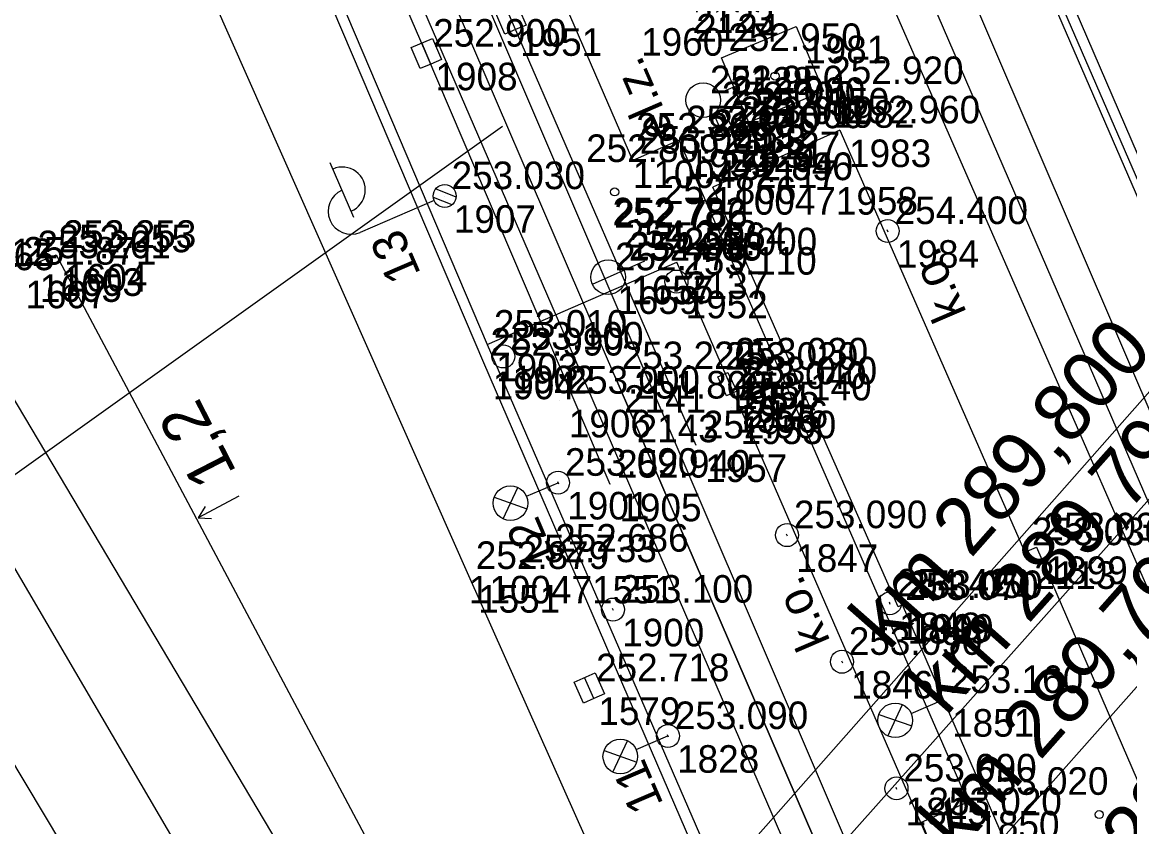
# Model space of a CAD drawing. Extents: x -496688 to -495455, y -1089309 to -1088026.
# Drawn here: x -496075.33 to -496027.15, y -1088401.59 to -1088366.58 of the extents above; entities that cross this region are included whole.
import ezdxf

# ---------------------------------------------------------------- set-up
doc = ezdxf.new("R2010")
doc.units = 0
for name, color, linetype in [('Vrstva 1', 7, 'Continuous'), ('Vrstva 13', 7, 'Continuous'), ('Vrstva 16', 7, 'Continuous'), ('Vrstva 17', 7, 'Continuous'), ('Vrstva 23', 7, 'Continuous'), ('Vrstva 25', 7, 'Continuous'), ('Vrstva 29', 7, 'Continuous'), ('Vrstva 36', 7, 'Continuous'), ('Vrstva 43', 7, 'Continuous'), ('Vrstva 47', 7, 'Continuous'), ('Vrstva 50', 7, 'Continuous'), ('Vrstva 51', 7, 'Continuous'), ('Vrstva 55', 7, 'Continuous'), ('Vrstva 59', 7, 'Continuous'), ('Vrstva 6', 7, 'Continuous'), ('Vrstva 60', 7, 'Continuous'), ('Vrstva 61', 7, 'Continuous')]:
    doc.layers.add(name, color=color, linetype=linetype)

msp = doc.modelspace()

# ---------------------------------------------------------------- linework, layer by layer
at = {"layer": 'Vrstva 1'}
for points in [[(-496002.91, -1088487.94), (-496012.12, -1088468.34), (-496019.16, -1088452.48), (-496027.13, -1088434.02), (-496033.75, -1088418.68), (-496038, -1088408.8), (-496049, -1088383.26), (-496049.55, -1088381.98), (-496058.24, -1088361.79), (-496064.07, -1088348.3)], [(-496001.99, -1088443.76), (-496010.04, -1088425.17), (-496041.61, -1088352.14), (-496042.12, -1088351.02)], [(-496016.532, -1088478.726), (-496026.498, -1088456.559), (-496035.879, -1088435.575), (-496046.648, -1088411.427), (-496055.896, -1088390.674), (-496071.432, -1088355.64)]]:
    msp.add_lwpolyline(points, dxfattribs=at)
at = {"layer": 'Vrstva 13'}
msp.add_line((-496065.907, -1088387.212), (-496067.673, -1088388.151), dxfattribs=at)
for points in [[(-496006.04, -1088421.27), (-496039.66, -1088343.83)], [(-496061.92, -1088348.13), (-496054.07, -1088366.45), (-496046.02, -1088384.99)], [(-496049.75, -1088386.7), (-496057.75, -1088367.95), (-496065.63, -1088349.73)], [(-496080.12, -1088377.498), (-496074.961, -1088377.155), (-496073.856, -1088376.703), (-496059.337, -1088404.014), (-496053.843, -1088414.068), (-496043.578, -1088433.154), (-496032.169, -1088453.826), (-496029.326, -1088459.298)], [(-496067.372, -1088387.651), (-496067.673, -1088388.151), (-496067.091, -1088388.181)]]:
    msp.add_lwpolyline(points, dxfattribs=at)
at = {"layer": 'Vrstva 16'}
for p, q in [((-496041.7, -1088339.8), (-495977.29, -1088488.74)), ((-496048.77, -1088372.6), (-496062.47, -1088340.95)), ((-496046.75, -1088371.72), (-496048.77, -1088372.6)), ((-496034.18, -1088400.5), (-496046.75, -1088371.72)), ((-496036.21, -1088401.39), (-496034.18, -1088400.5))]:
    msp.add_line(p, q, dxfattribs=at)
for points in [[(-496079.26, -1088341.75), (-496070.21, -1088346.6), (-496069.83, -1088346), (-496055.11, -1088380.61)], [(-496036.29, -1088409.7), (-496064.15, -1088344.68), (-496066.65, -1088345.76), (-496038.55, -1088410.67)], [(-496040.8, -1088349.66), (-495980.44, -1088490.38), (-495970.84, -1088512.75)], [(-496043.99, -1088350.95), (-496001.7, -1088447.58), (-495982.81, -1088491.28), (-495972.63, -1088514.67), (-495960.36, -1088543.09), (-495953.91, -1088556.79), (-495957.95, -1088558.44), (-495964.6, -1088544.16), (-495976.56, -1088516.39), (-495986.4, -1088493.44), (-495993.77, -1088476.63), (-495996.44, -1088470.15), (-496005.77, -1088448.81)], [(-496049.55, -1088381.98), (-496049, -1088383.26), (-496038, -1088408.8), (-496037.45, -1088410.08)], [(-496036.21, -1088401.39), (-496032.08, -1088411.59)]]:
    msp.add_lwpolyline(points, dxfattribs=at)
at = {"layer": 'Vrstva 17'}
msp.add_lwpolyline([(-496095, -1088344.78), (-496090.4, -1088338.56), (-496087.52, -1088339.34), (-496079.62, -1088343.92), (-496077.74, -1088344.53), (-496072.27, -1088346.17), (-496070.01, -1088346.79), (-496055.26, -1088381.39), (-496028.35, -1088443.67), (-496017.15, -1088468.64), (-496004.62, -1088495.93), (-495995.82, -1088511.25), (-495975.79, -1088547.86), (-495946.8, -1088592.09), (-495933.46, -1088582.38), (-495946.67, -1088555.94), (-495952.97, -1088543.38), (-495959.99, -1088527.36), (-495989.63, -1088458.09), (-496005.03, -1088422.44), (-496022.96, -1088381.24), (-496041.83, -1088337.51), (-496069.73, -1088316.93)], dxfattribs=at)
at = {"layer": 'Vrstva 23'}
for p, q in [((-496044.91, -1088368.14), (-496041.67, -1088366.77)), ((-496055.11, -1088380.61), (-496046.85, -1088377.03))]:
    msp.add_line(p, q, dxfattribs=at)
for points in [[(-496041.67, -1088366.77), (-496040.48, -1088369.58), (-496043.72, -1088370.95), (-496044.91, -1088368.14)], [(-496039.76, -1088371.29), (-496045.29, -1088373.76)], [(-496039.76, -1088371.29), (-496031.71, -1088389.64), (-496031.21, -1088389.43), (-496005.59, -1088448.65)], [(-496037.22, -1088392.02), (-496045.29, -1088373.76)], [(-496055.11, -1088380.61), (-496040.15, -1088415.06), (-496031.83, -1088411.54), (-496046.85, -1088377.03)], [(-496029.66, -1088408.99), (-496037.04, -1088391.94), (-496037.22, -1088392.02)]]:
    msp.add_lwpolyline(points, dxfattribs=at)
at = {"layer": 'Vrstva 25'}
for p, q in [((-496060.901, -1088375.088), (-496061.929, -1088372.7)), ((-496056.454, -1088374.197), (-496057.344, -1088373.843)), ((-496057.409, -1088374.348), (-496060.624, -1088375.731)), ((-496056.627, -1088374.531), (-496057.444, -1088374.206)), ((-496037.66, -1088375.716), (-496037.7, -1088375.624)), ((-496054.413, -1088388.191), (-496053.775, -1088386.825)), ((-496053.398, -1088387.213), (-496052.02, -1088386.62)), ((-496054.8, -1088387.252), (-496053.377, -1088387.753)), ((-496037.571, -1088391.916), (-496037.609, -1088391.824)), ((-496036.658, -1088396.663), (-496035.28, -1088396.07)), ((-496037.673, -1088397.641), (-496037.035, -1088396.275)), ((-496038.06, -1088396.702), (-496036.637, -1088397.203)), ((-496049.633, -1088399.211), (-496048.995, -1088397.845)), ((-496048.618, -1088398.233), (-496047.24, -1088397.64)), ((-496050.02, -1088398.272), (-496048.597, -1088398.773))]:
    msp.add_line(p, q, dxfattribs=at)
for centre, radius in [((-496056.95, -1088374.15), 0.5), ((-496056.95, -1088374.15), 0.5), ((-496037.68, -1088375.67), 0.5), ((-496054.091, -1088387.509), 0.754), ((-496037.59, -1088391.87), 0.5), ((-496037.351, -1088396.959), 0.754), ((-496049.311, -1088398.529), 0.754)]:
    msp.add_circle(centre, radius, dxfattribs=at)
for centre, start, end in [((-496061.404, -1088373.889), 292.585, 113.9902), ((-496061.019, -1088374.813), 113.2876, 293.2876)]:
    msp.add_arc(centre, 1, start, end, dxfattribs=at)
at = {"layer": 'Vrstva 29'}
msp.add_lwpolyline([(-496089.818, -1088342.239), (-496104.91, -1088361.836), (-496082.668, -1088391.264), (-496054.437, -1088371.109)], dxfattribs=at)
at = {"layer": 'Vrstva 36'}
msp.add_line((-496045.015, -1088369.681), (-496044.097, -1088369.284), dxfattribs=at)
for points in [[(-496045.2, -1088370.67), (-496044.76, -1088370.49), (-496044.41, -1088371.32), (-496044.84, -1088371.5), (-496045.2, -1088370.67)], [(-496045.07, -1088382.01), (-496044.63, -1088381.82), (-496044.24, -1088382.64), (-496044.7, -1088382.84), (-496045.07, -1088382.01)]]:
    msp.add_lwpolyline(points, dxfattribs=at)
msp.add_circle((-496045.71, -1088369.979), 0.757, dxfattribs=at)
at = {"layer": 'Vrstva 43'}
for points in [[(-496053.872, -1088366.909), (-496054.332, -1088367.107), (-496054.727, -1088366.188), (-496053.808, -1088365.793), (-496053.413, -1088366.712), (-496053.872, -1088366.909), (-496054.268, -1088365.991)], [(-496057.552, -1088368.409), (-496058.012, -1088368.607), (-496058.407, -1088367.688), (-496057.488, -1088367.293), (-496057.093, -1088368.212), (-496057.552, -1088368.409), (-496057.948, -1088367.491)], [(-496050.463, -1088396.016), (-496050.92, -1088396.219), (-496051.326, -1088395.305), (-496050.412, -1088394.899), (-496050.006, -1088395.813), (-496050.463, -1088396.016), (-496050.869, -1088395.102)]]:
    msp.add_lwpolyline(points, dxfattribs=at)
at = {"layer": 'Vrstva 47'}
msp.add_line((-496050.526, -1088377.981), (-496048.238, -1088376.975), dxfattribs=at)
msp.add_circle((-496049.84, -1088377.679), 0.75, dxfattribs=at)
at = {"layer": 'Vrstva 50'}
for p, q in [((-496046.85, -1088377.916), (-496046.89, -1088377.824)), ((-496054.38, -1088381.176), (-496054.42, -1088381.084)), ((-496052.04, -1088386.574), (-496052, -1088386.666)), ((-496042.04, -1088388.946), (-496042.08, -1088388.854)), ((-496049.61, -1088392.186), (-496049.65, -1088392.094)), ((-496039.69, -1088394.364), (-496039.65, -1088394.456)), ((-496047.22, -1088397.686), (-496047.26, -1088397.594)), ((-496037.28, -1088399.966), (-496037.32, -1088399.874))]:
    msp.add_line(p, q, dxfattribs=at)
for centre in [(-496046.87, -1088377.87), (-496054.4, -1088381.13), (-496052.02, -1088386.62), (-496042.06, -1088388.9), (-496049.63, -1088392.14), (-496039.67, -1088394.41), (-496047.24, -1088397.64), (-496037.3, -1088399.92)]:
    msp.add_circle(centre, 0.5, dxfattribs=at)
at = {"layer": 'Vrstva 51'}
msp.add_lwpolyline([(-495977.447, -1088558.133), (-495981.17, -1088560.671), (-496005.397, -1088519.367), (-496022.661, -1088489.693), (-496025.004, -1088485.709), (-496027.464, -1088481.551), (-496045.275, -1088451.173), (-496063.404, -1088419.387), (-496086.159, -1088381.351), (-496097.371, -1088363.41), (-496092.898, -1088360.245), (-496082.247, -1088379.121), (-496059.799, -1088417.46), (-496050.414, -1088433.44), (-496038.244, -1088454.083), (-496022.567, -1088481.185), (-496019.429, -1088486.595), (-496001.625, -1088516.799), (-495977.447, -1088558.133)], dxfattribs=at)
at = {"layer": 'Vrstva 55'}
msp.add_lwpolyline([(-495954.14, -1088589.68), (-495962.8, -1088574.76), (-495975.81, -1088551.75), (-495980.15, -1088535.95), (-495988.3, -1088530.08), (-496096.94, -1088347.2)], dxfattribs=at)
at = {"layer": 'Vrstva 59'}
for centre in [(-496042.583, -1088368.932), (-496049.557, -1088373.972), (-496028.482, -1088401.057)]:
    msp.add_circle(centre, 0.175, dxfattribs=at)
at = {"layer": 'Vrstva 6'}
for p, q in [((-496127.419, -1088497.214), (-496021.846, -1088377.607)), ((-496094.37, -1088463.824), (-496019.966, -1088380.195)), ((-496084.128, -1088460.218), (-496019.428, -1088387.106))]:
    msp.add_line(p, q, dxfattribs=at)
at = {"layer": 'Vrstva 60'}
for p, q in [((-496041.67, -1088366.77), (-496041.67, -1088366.77)), ((-496057.75, -1088367.95), (-496057.75, -1088367.95)), ((-496044.91, -1088368.14), (-496044.91, -1088368.14)), ((-496040.48, -1088369.58), (-496040.48, -1088369.58)), ((-496045.71, -1088369.98), (-496045.71, -1088369.98)), ((-496044.76, -1088370.49), (-496044.76, -1088370.49)), ((-496045.2, -1088370.67), (-496045.2, -1088370.67)), ((-496043.72, -1088370.95), (-496043.72, -1088370.95)), ((-496044.84, -1088371.5), (-496044.84, -1088371.5)), ((-496044.41, -1088371.32), (-496044.41, -1088371.32)), ((-496039.76, -1088371.29), (-496039.76, -1088371.29)), ((-496046.75, -1088371.72), (-496046.75, -1088371.72)), ((-496048.77, -1088372.6), (-496048.77, -1088372.6)), ((-496045.29, -1088373.76), (-496045.29, -1088373.76)), ((-496056.95, -1088374.15), (-496056.95, -1088374.15)), ((-496037.68, -1088375.67), (-496037.68, -1088375.67)), ((-496073.856, -1088376.703), (-496073.856, -1088376.703)), ((-496073.856, -1088376.703), (-496073.856, -1088376.703)), ((-496074.961, -1088377.155), (-496074.961, -1088377.155)), ((-496074.961, -1088377.155), (-496074.961, -1088377.155)), ((-496074.047, -1088376.895), (-496074.047, -1088376.895)), ((-496074.047, -1088376.895), (-496074.047, -1088376.895)), ((-496049.244, -1088377.259), (-496049.244, -1088377.259)), ((-496049.244, -1088377.259), (-496049.244, -1088377.259)), ((-496049.224, -1088377.211), (-496049.224, -1088377.211)), ((-496049.224, -1088377.211), (-496049.224, -1088377.211)), ((-496046.85, -1088377.03), (-496046.85, -1088377.03)), ((-496049.84, -1088377.679), (-496049.84, -1088377.679)), ((-496049.84, -1088377.679), (-496049.84, -1088377.679)), ((-496046.87, -1088377.87), (-496046.87, -1088377.87)), ((-496055.11, -1088380.61), (-496055.11, -1088380.61)), ((-496054.4, -1088381.13), (-496054.4, -1088381.13)), ((-496055.26, -1088381.39), (-496055.26, -1088381.39)), ((-496049.55, -1088381.98), (-496049.55, -1088381.98)), ((-496045.07, -1088382.01), (-496045.07, -1088382.01)), ((-496044.63, -1088381.82), (-496044.63, -1088381.82)), ((-496051.95, -1088383.05), (-496051.95, -1088383.05)), ((-496044.7, -1088382.84), (-496044.7, -1088382.84)), ((-496044.24, -1088382.64), (-496044.24, -1088382.64)), ((-496049, -1088383.26), (-496049, -1088383.26)), ((-496044.48, -1088383.34), (-496044.48, -1088383.34)), ((-496046.02, -1088384.99), (-496046.02, -1088384.99)), ((-496052.02, -1088386.62), (-496052.02, -1088386.62)), ((-496049.75, -1088386.7), (-496049.75, -1088386.7)), ((-496042.06, -1088388.9), (-496042.06, -1088388.9)), ((-496031.71, -1088389.64), (-496031.71, -1088389.64)), ((-496031.21, -1088389.43), (-496031.21, -1088389.43)), ((-496055.896, -1088390.674), (-496055.896, -1088390.674)), ((-496055.896, -1088390.674), (-496055.896, -1088390.674)), ((-496049.63, -1088392.14), (-496049.63, -1088392.14)), ((-496037.59, -1088391.87), (-496037.59, -1088391.87)), ((-496037.22, -1088392.02), (-496037.22, -1088392.02)), ((-496037.04, -1088391.94), (-496037.04, -1088391.94)), ((-496039.67, -1088394.41), (-496039.67, -1088394.41)), ((-496050.666, -1088395.559), (-496050.666, -1088395.559)), ((-496050.666, -1088395.559), (-496050.666, -1088395.559)), ((-496035.28, -1088396.07), (-496035.28, -1088396.07)), ((-496047.24, -1088397.64), (-496047.24, -1088397.64)), ((-496037.3, -1088399.92), (-496037.3, -1088399.92)), ((-496034.18, -1088400.5), (-496034.18, -1088400.5)), ((-496036.21, -1088401.39), (-496036.21, -1088401.39))]:
    msp.add_line(p, q, dxfattribs=at)

# ---------------------------------------------------------------- texts
at = {"layer": 'Vrstva 13'}
msp.add_text('1,2', height=2, rotation=117.1833, dxfattribs=at).set_placement((-496065.982, -1088386.168))
at = {"layer": 'Vrstva 25'}
for s, rotation, p in [('13', 113.2876, (-496057.973, -1088377.534)), ('k.o.', 113.2876, (-496034.234, -1088379.22)), ('12', 113.3014, (-496052.048, -1088390.044)), ('k.o.', 113.3014, (-496040.161, -1088393.516)), ('11', 113.3014, (-496047.421, -1088400.603))]:
    msp.add_text(s, height=1.5, rotation=rotation, dxfattribs=at).set_placement(p)
at = {"layer": 'Vrstva 36'}
for rotation, p in [(113.4481, (-496046.967, -1088371.346)), (114.0265, (-496041.91, -1088383.513))]:
    msp.add_text('el.z.', height=1.5, rotation=rotation, dxfattribs=at).set_placement(p)
at = {"layer": 'Vrstva 6'}
for s, rotation, p in [('km 289,800', 48.5663, (-496037.635, -1088393.984)), ('km 289,798', 48.341, (-496035.151, -1088396.823)), ('km 289,792', 48.493, (-496034.634, -1088402.78)), ('km 289,786', 48.7353, (-496030.277, -1088407.42)), ('km 289,785', 48.6063, (-496027.113, -1088410.465))]:
    msp.add_text(s, height=2.5, rotation=rotation, dxfattribs=at).set_placement(p)
at = {"layer": 'Vrstva 60'}
for s, p in [('2123', (-496046.18, -1088367.05)), ('2124', (-496046.01, -1088367.43)), ('1951', (-496053.67, -1088368.05)), ('1960', (-496048.405, -1088368.044)), ('1981', (-496041.27, -1088368.37)), ('1908', (-496057.35, -1088369.55)), ('2128', (-496044.51, -1088369.74)), ('1982', (-496040.08, -1088371.18)), ('2130', (-496045.31, -1088371.58)), ('2133', (-496044.8, -1088372.27)), ('2132', (-496044.36, -1088372.09)), ('2127', (-496043.32, -1088372.55)), ('2129', (-496044.44, -1088373.1)), ('2131', (-496044.01, -1088372.92)), ('1983', (-496039.36, -1088372.89)), ('1959', (-496046.35, -1088373.32)), ('1100472117', (-496048.77, -1088373.8)), ('1100471958', (-496045.29, -1088374.96)), ('1907', (-496056.55, -1088375.75)), ('1984', (-496037.28, -1088377.27)), ('1603', (-496073.647, -1088378.495)), ('1603', (-496073.647, -1088378.495)), ('1604', (-496073.456, -1088378.303)), ('1604', (-496073.456, -1088378.303)), ('1605', (-496074.561, -1088378.755)), ('1605', (-496074.561, -1088378.755)), ('1657', (-496048.844, -1088378.859)), ('1657', (-496048.844, -1088378.859)), ('1655', (-496048.824, -1088378.811)), ('1655', (-496048.824, -1088378.811)), ('2137', (-496046.45, -1088378.63)), ('1607', (-496075.189, -1088379.033)), ('1607', (-496075.189, -1088379.033)), ('1659', (-496049.44, -1088379.279)), ('1659', (-496049.44, -1088379.279)), ('1952', (-496046.47, -1088379.47)), ('1903', (-496054.71, -1088382.21)), ('1902', (-496054, -1088382.73)), ('1904', (-496054.86, -1088382.99)), ('2141', (-496049.15, -1088383.58)), ('1954', (-496044.67, -1088383.61)), ('1955', (-496044.23, -1088383.42)), ('2146', (-496043.84, -1088384.24)), ('1906', (-496051.55, -1088384.65)), ('1956', (-496044.3, -1088384.44)), ('2143', (-496048.6, -1088384.86)), ('1953', (-496044.08, -1088384.94)), ('1957', (-496045.62, -1088386.59)), ('1901', (-496051.62, -1088388.22)), ('1905', (-496049.35, -1088388.3)), ('1847', (-496041.66, -1088390.5)), ('1899', (-496030.81, -1088391.03)), ('2113', (-496031.31, -1088391.24)), ('1100471551', (-496055.896, -1088391.874)), ('1551', (-496055.496, -1088392.274)), ('1848', (-496037.19, -1088393.47)), ('1900', (-496049.23, -1088393.74)), ('1849', (-496036.82, -1088393.62)), ('1999', (-496036.64, -1088393.54)), ('1846', (-496039.27, -1088396.01)), ('1579', (-496050.266, -1088397.159)), ('1579', (-496050.266, -1088397.159)), ('1851', (-496034.88, -1088397.67)), ('1828', (-496046.84, -1088399.24)), ('1845', (-496036.9, -1088401.52)), ('1850', (-496033.78, -1088402.1))]:
    msp.add_text(s, height=1.2, dxfattribs=at).set_placement(p)
at = {"layer": 'Vrstva 61'}
for s, p in [('252.900', (-496057.45, -1088367.65)), ('252.950', (-496044.61, -1088367.84)), ('252.920', (-496040.18, -1088369.28)), ('252.950', (-496045.41, -1088369.68)), ('253.000', (-496044.46, -1088370.19)), ('253.000', (-496044.9, -1088370.37)), ('252.950', (-496043.42, -1088370.65)), ('253.000', (-496044.54, -1088371.2)), ('253.000', (-496044.11, -1088371.02)), ('252.960', (-496039.46, -1088370.99)), ('252.866', (-496048.624, -1088371.74)), ('253.040', (-496046.45, -1088371.42)), ('252.809', (-496050.796, -1088372.669)), ('253.000', (-496048.47, -1088372.3)), ('252.846', (-496045.001, -1088373.451)), ('252.990', (-496044.99, -1088373.46)), ('253.030', (-496056.65, -1088373.85)), ('252.866', (-496047.458, -1088374.498)), ('252.782', (-496049.653, -1088375.426)), ('252.786', (-496049.575, -1088375.527)), ('254.400', (-496037.38, -1088375.37)), ('252.055', (-496073.747, -1088376.595)), ('252.055', (-496073.747, -1088376.595)), ('253.253', (-496073.556, -1088376.403)), ('253.253', (-496073.556, -1088376.403)), ('254.242', (-496049.155, -1088376.401)), ('252.964', (-496047.898, -1088376.498)), ('253.261', (-496074.661, -1088376.855)), ('253.261', (-496074.661, -1088376.855)), ('252.805', (-496048.944, -1088376.959)), ('252.805', (-496048.944, -1088376.959)), ('254.256', (-496048.924, -1088376.911)), ('254.256', (-496048.924, -1088376.911)), ('253.000', (-496046.55, -1088376.73)), ('252.812', (-496079.82, -1088377.198)), ('252.812', (-496079.82, -1088377.198)), ('251.765', (-496079.718, -1088377.376)), ('251.765', (-496079.718, -1088377.376)), ('251.871', (-496075.289, -1088377.133)), ('251.871', (-496075.289, -1088377.133)), ('252.779', (-496049.54, -1088377.379)), ('252.779', (-496049.54, -1088377.379)), ('253.110', (-496046.57, -1088377.57)), ('253.010', (-496054.81, -1088380.31)), ('253.100', (-496054.1, -1088380.83)), ('252.990', (-496054.96, -1088381.09)), ('253.220', (-496049.25, -1088381.68)), ('253.020', (-496044.77, -1088381.71)), ('253.030', (-496044.33, -1088381.52)), ('253.020', (-496043.94, -1088382.34)), ('253.000', (-496051.65, -1088382.75)), ('253.040', (-496044.4, -1088382.54)), ('251.800', (-496048.7, -1088382.96)), ('253.140', (-496044.18, -1088383.04)), ('252.960', (-496045.72, -1088384.69)), ('253.090', (-496051.72, -1088386.32)), ('252.940', (-496049.45, -1088386.4)), ('253.090', (-496041.76, -1088388.6)), ('253.030', (-496030.91, -1088389.13)), ('252.686', (-496052.142, -1088389.62)), ('253.030', (-496031.41, -1088389.34)), ('252.733', (-496053.523, -1088390.078)), ('252.879', (-496055.596, -1088390.374)), ('252.879', (-496055.596, -1088390.374)), ('253.100', (-496049.33, -1088391.84)), ('254.420', (-496037.29, -1088391.57)), ('253.070', (-496036.92, -1088391.72)), ('253.050', (-496036.74, -1088391.64)), ('253.090', (-496039.37, -1088394.11)), ('252.718', (-496050.366, -1088395.259)), ('252.718', (-496050.366, -1088395.259)), ('253.160', (-496034.98, -1088395.77)), ('253.090', (-496046.94, -1088397.34)), ('253.090', (-496037, -1088399.62)), ('253.020', (-496033.88, -1088400.2)), ('253.020', (-496035.91, -1088401.09))]:
    msp.add_text(s, height=1.2, dxfattribs=at).set_placement(p)

doc.saveas('drawing.dxf')
